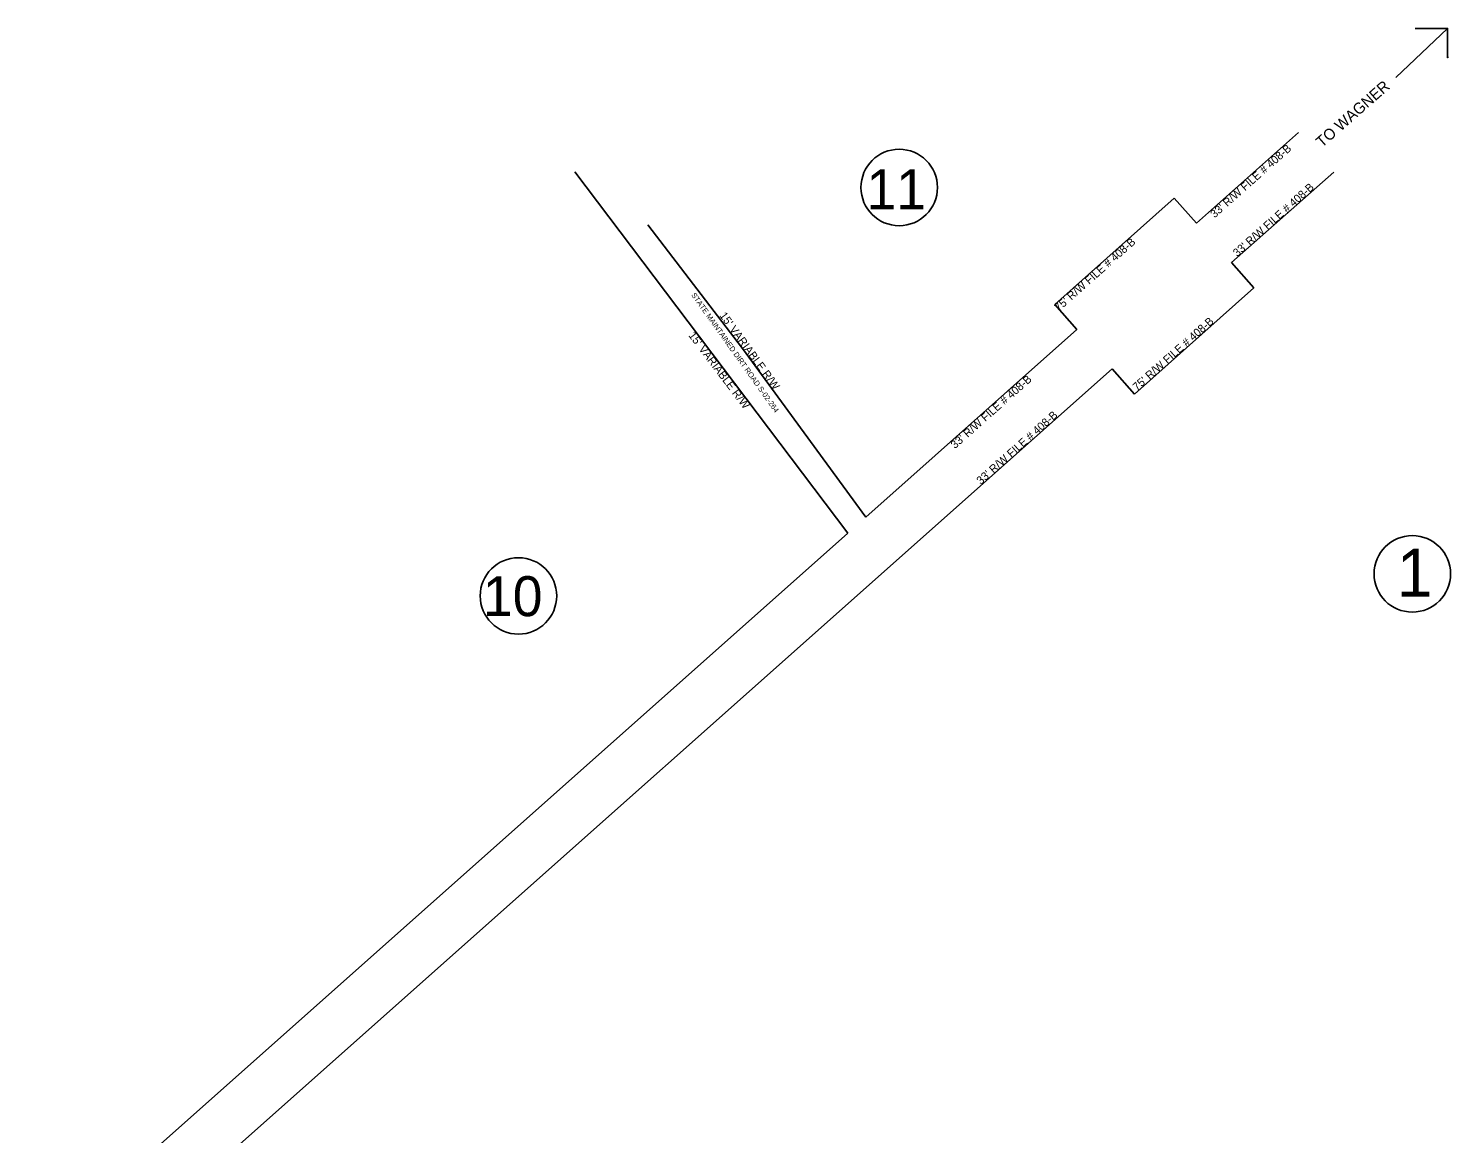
# Model space of a CAD drawing. Extents: x 50032 to 55703, y 49604 to 53496.
# Drawn here: x 53925 to 55703, y 52114 to 53496 of the extents above; entities that cross this region are included whole.
import ezdxf

# ---------------------------------------------------------------- set-up
doc = ezdxf.new("R2010")
doc.units = 0
doc.layers.add('Level 12', color=7, linetype='Continuous')
doc.layers.add('Level 25', color=7, linetype='Continuous')

msp = doc.modelspace()

# ---------------------------------------------------------------- linework, layer by layer
at = {"layer": 'Level 12'}
for p, q in [((55385.2, 53252.2), (55512.7, 53365.5)), ((54949.4, 52864.8), (54608.2, 53316.5)), ((55429, 53202.9), (55556.5, 53316.2)), ((55207.8, 53150.7), (55357.3, 53283.6)), ((55357.3, 53283.6), (55385.2, 53252.2)), ((54817.7, 53095.6), (54699.2, 53250)), ((55429, 53202.9), (55456.9, 53171.5)), ((55456.9, 53171.5), (55307.4, 53038.6)), ((55235.7, 53119.3), (55207.8, 53150.7)), ((54971.8, 52884.8), (55235.7, 53119.3)), ((54971.8, 52884.8), (54817.7, 53095.6)), ((55279.5, 53070), (53969, 51905.1)), ((55307.4, 53038.6), (55279.5, 53070)), ((54949.4, 52864.8), (53925.2, 51954.4))]:
    msp.add_line(p, q, dxfattribs=at)
at = {"layer": 'Level 25'}
for points in [[(55634, 53434.5), (55698.8, 53495.7), (55658.4, 53495.7)], [(55698.8, 53495.7), (55698.8, 53495.7), (55698.8, 53459), (55700, 53460.2)]]:
    msp.add_lwpolyline(points, dxfattribs=at)
for centre in [(55013.5, 53296.9), (55654.8, 52813.8), (54537.6, 52786.2)]:
    msp.add_circle(centre, 47.8, dxfattribs=at)

# ---------------------------------------------------------------- texts
for s, height, rotation, p in [('TO WAGNER', 13.86, 41.2602, (55541.9, 53346.1)), ("33' R/W FILE # 408-B", 10, 41.6333, (55407.7, 53258.2)), ("33' R/W FILE # 408-B", 10, 41.6333, (55436, 53209.7)), ("75' R/W FILE # 408-B", 10, 41.6333, (55212.9, 53141.3)), ('STATE MAINTAINED DIRT ROAD S-02-264', 6.615, 305.4558, (54753.2, 53162.3)), ("15' VARIABLE R/W", 10, 306.157, (54788.3, 53136.7)), ("75' R/W FILE # 408-B", 10, 41.6333, (55310.7, 53042.1)), ("15' VARIABLE R/W", 10, 307.0661, (54749.6, 53111.8)), ("33' R/W FILE # 408-B", 10, 41.6333, (55083.2, 52969.7)), ("33' R/W FILE # 408-B", 10, 41.6333, (55115.5, 52924.9))]:
    msp.add_text(s, height=height, rotation=rotation, dxfattribs=at).set_placement(p)
for s, height, p in [('11', 50, (54972.7, 53269.7)), ('1', 60, (55635.3, 52785.2)), ('10', 50, (54493.3, 52760.9))]:
    msp.add_text(s, height=height, dxfattribs=at).set_placement(p)

doc.saveas('drawing.dxf')
